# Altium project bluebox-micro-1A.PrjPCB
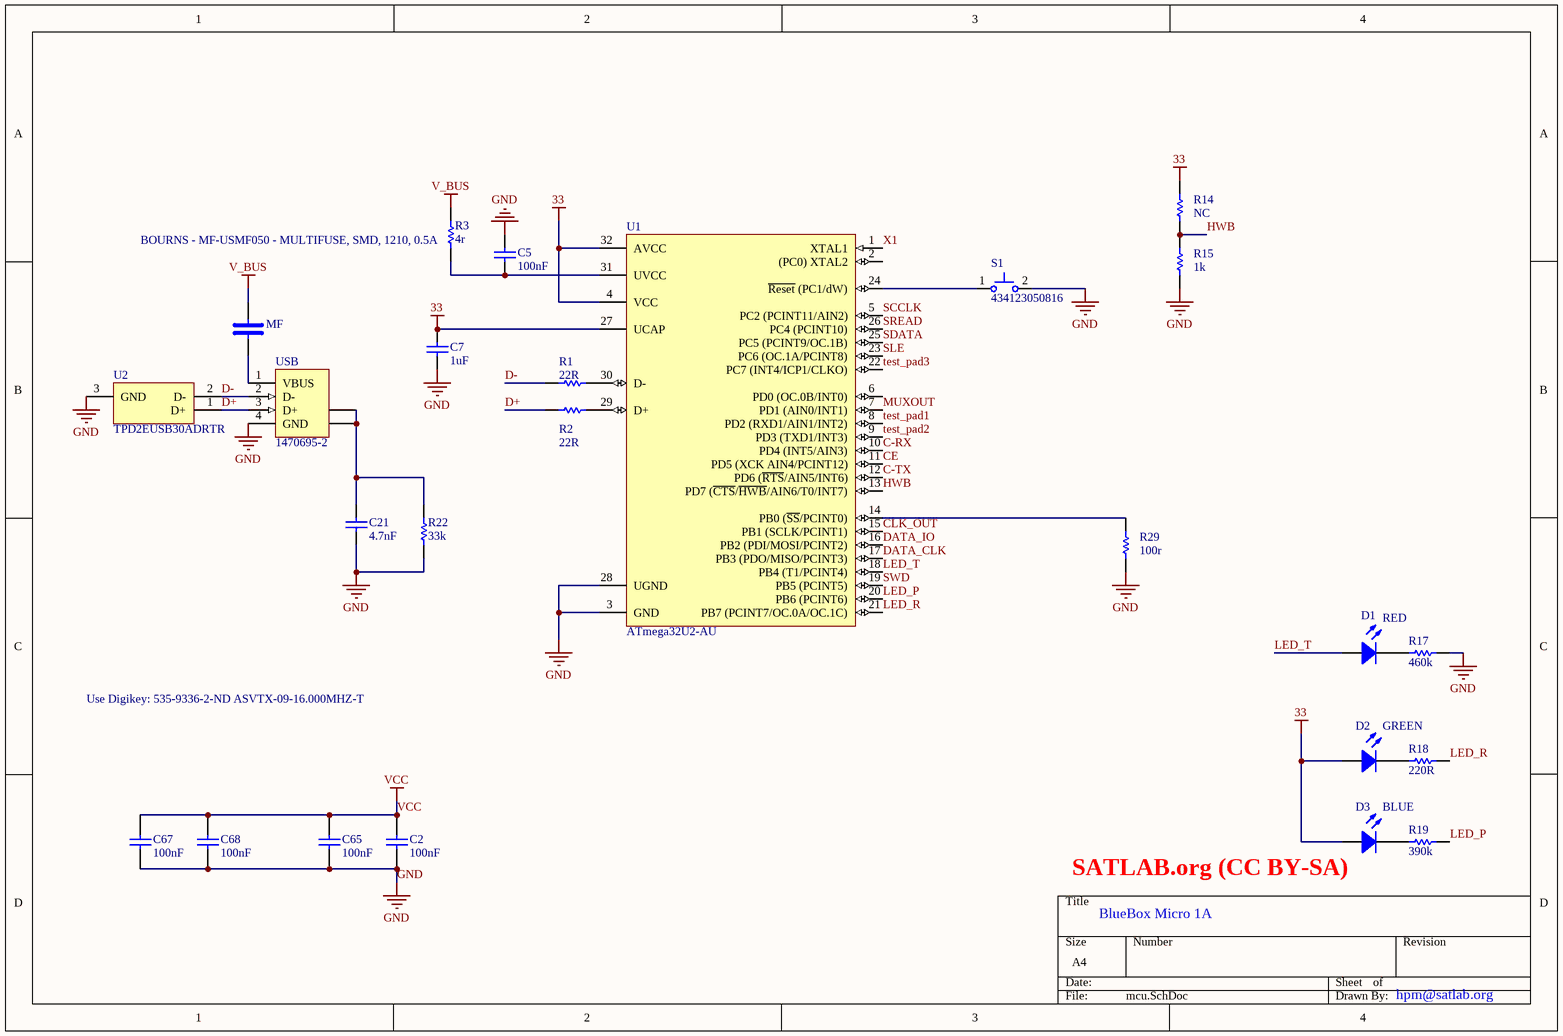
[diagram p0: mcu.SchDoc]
3 sheets, 97 parts. Net scope: global (net labels, ports and power ports of the same name join across sheets).
Board file: bluebox-micro-1A.PcbDoc
Sheets:
  mcu.SchDoc
  transceiver.SchDoc
  misc_rf.SchDoc

## Sheet mcu.SchDoc
size A4

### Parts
C2  value 100nF  [C06]  (hidden comment: Capacitor)
C5  value 100nF  [C06]  (hidden comment: Cap Semi)
C7  value 1uF  [C06]  (hidden comment: Cap Semi)
C21  value 4.7nF  [C06]  (hidden comment: Cap Semi)
C65  value 100nF  [C06]  (hidden comment: Capacitor)
C67  value 100nF  [C06]  (hidden comment: Capacitor)
C68  value 100nF  [C06]  (hidden comment: Capacitor)
D1  RED  [L06]
D2  GREEN  [L06]
D3  BLUE  [L06]
MF  CapacitorBig  [C1210]  (value not drawn)
R1  value 22R  [R06]  (hidden comment: Resistor)
R2  value 22R  [R06]  (hidden comment: Resistor)
R3  value 4r  [R06]  (hidden comment: Resistor)
R14  value NC  [R06]  (hidden comment: Resistor)
R15  value 1k  [R06]  (hidden comment: Resistor)
R17  value 460k  [R06]  (hidden comment: Resistor)
R18  value 220R  [R06]  (hidden comment: Resistor)
R19  value 390k  [R06]  (hidden comment: Resistor)
R22  value 33k  [R06]  (hidden comment: Resistor)
R29  value 100r  [R06]  (hidden comment: Resistor)
S1  434123050816  [spsd-raised]
U1  ATmega32U2-AU  [32A_L]
U2  TPD2EUSB30ADRTR  [DRT3]
USB  1470695-2  [1470695A]

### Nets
GND: C2.1 C5.1 C7.2 C21.2 C65.1 C67.1 C68.1 R15.1 R17.1 R22.2 R29.1 S1.2 U1.3(GND) U1.28(UGND) U2.3(GND) USB.4(GND)
V_BUS: MF.1 R3.1
VCC: C2.2 C7.1 C65.2 C67.2 C68.2 D2.1(A) D3.1(A) R14.2 U1.4(VCC) U1.27(UCAP) U1.32(AVCC)  [also labelled 33]
C-RX: U1.10(PD4_(INT5/AIN3))
C-TX: U1.12(PD6_(~{RTS}/AIN5/INT6))
CE: U1.11(PD5_(XCK_AIN4/PCINT12))
CLK_OUT: U1.15(PB1_(SCLK/PCINT1))
D+: R2.1 U2.1(D+) USB.3(D+)
D-: R1.2 U2.2(D-) USB.2(D-)
DATA_CLK: U1.17(PB3_(PDO/MISO/PCINT3))
DATA_IO: U1.16(PB2_(PDI/MOSI/PCINT2))
HWB: R14.1 R15.2 U1.13(PD7_(~{CTS}/~{HWB}/AIN6/T0/INT7))
LED_P: R19.1 U1.20(PB6_(PCINT6))
LED_R: R18.1 U1.21(PB7_(PCINT7/OC.0A/OC.1C))
LED_T: D1.1(A) U1.18(PB4_(T1/PCINT4))
MUXOUT: U1.7(PD1_(AIN0/INT1))
SCCLK: U1.5(PC2_(PCINT11/AIN2))
SDATA: U1.25(PC5_(PCINT9/OC.1B))
SLE: U1.23(PC6_(OC.1A/PCINT8))
SREAD: U1.26(PC4_(PCINT10))
SWD: U1.19(PB5_(PCINT5))
test_pad1: U1.8(PD2_(RXD1/AIN1/INT2))
test_pad2: U1.9(PD3_(TXD1/INT3))
test_pad3: U1.22(PC7_(INT4/ICP1/CLKO))
X1: U1.1(XTAL1)
NetC5_2: C5.2 R3.2 U1.31(UVCC)
NetC21_1: C21.1 R22.1 USB.5(SHLD) USB.6(SHLD)
NetD1_2: D1.2(K) R17.2
NetD2_2: D2.2(K) R18.2
NetD3_2: D3.2(K) R19.2
NetMF_2: MF.2 USB.1(VBUS)
NetR1_1: R1.1 U1.30(D-)
NetR2_2: R2.2 U1.29(D+)
NetR29_2: R29.2 U1.14(PB0_(~{SS}/PCINT0))
NetS1_1: S1.1 U1.24(~{Reset}_(PC1/dW))

Not connected (* = marked no-connect by the designer): U1 2((PC0)_XTAL2) 6(PD0_(OC.0B/INT0))

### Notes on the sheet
- (near R3) BOURNS - MF-USMF050 - MULTIFUSE, SMD, 1210, 0.5A
- Use Digikey: 535-9336-2-ND ASVTX-09-16.000MHZ-T
- (near D3) SATLAB.org (CC BY-SA)
- BlueBox Micro 1A
- hpm@satlab.org

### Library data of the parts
C2 C65 C67 C68 = Capacitor: Capacitor, standard
C5 C7 C21 = Cap Semi: Capacitor (Semiconductor SIM Model)
D1-D3 = LED: Typical RED GaAs LED
MF = CapacitorBig: Capacitor for PRU etc.; By: Troels Jessen; Username: tjessen
R1-R3 R14 R15 R17-R19 R22 R29 = Resistor: By: Troels Jessen; Username: tjessen
S1 = spsd-raised: Switch, Subminiature SMT, WURTH ELEKTRONIK - 434123050816 - SWITCH, 160GF, 6X3.5X5MM, BLK, J-BEND
U1 = ATmega32U2-AU: 8-bit AVR Microcontroller, 2.7-5.5V, 32KB Flash, 1KB EEPROM, 1KB SRAM, 32-pin TQFP, Industrial Grade (-40°C to 85°C)
U2 = TPD2EUSB30ADRTR: ESD / Surge Solution for High Speed, Low Voltage Interface, 2 Channels, -40 to +85 degC, 3-pin SOT (DRT), Green (RoHS & no Sb/Br); Manufacturer: Texas Instruments; 1394 / Firewire: TRUE; Breakdown Voltage(Min)(V): 4.5; Differential Capacitance(pF): 0.05; IEC 61000-4-2 Air-Gap(+/- kV): 8; IO Capacitance(Typ)(pF): 0.7; IO Leakage Current(nA): 10; SubFamily: ESD Solution
USB = 1470695-2: USB 1.1, Right Angle, SMT, A Type, Plug, 4 Position, Natural; ContactMaterial: Brass; ContactPlating: Gold (30) over Nickel (50); PCB_Layout: Complies with manufacturer's recommendation.; DrillSize: Corresponds to nominal value.; PanelGround: Without

## Sheet transceiver.SchDoc
size A3
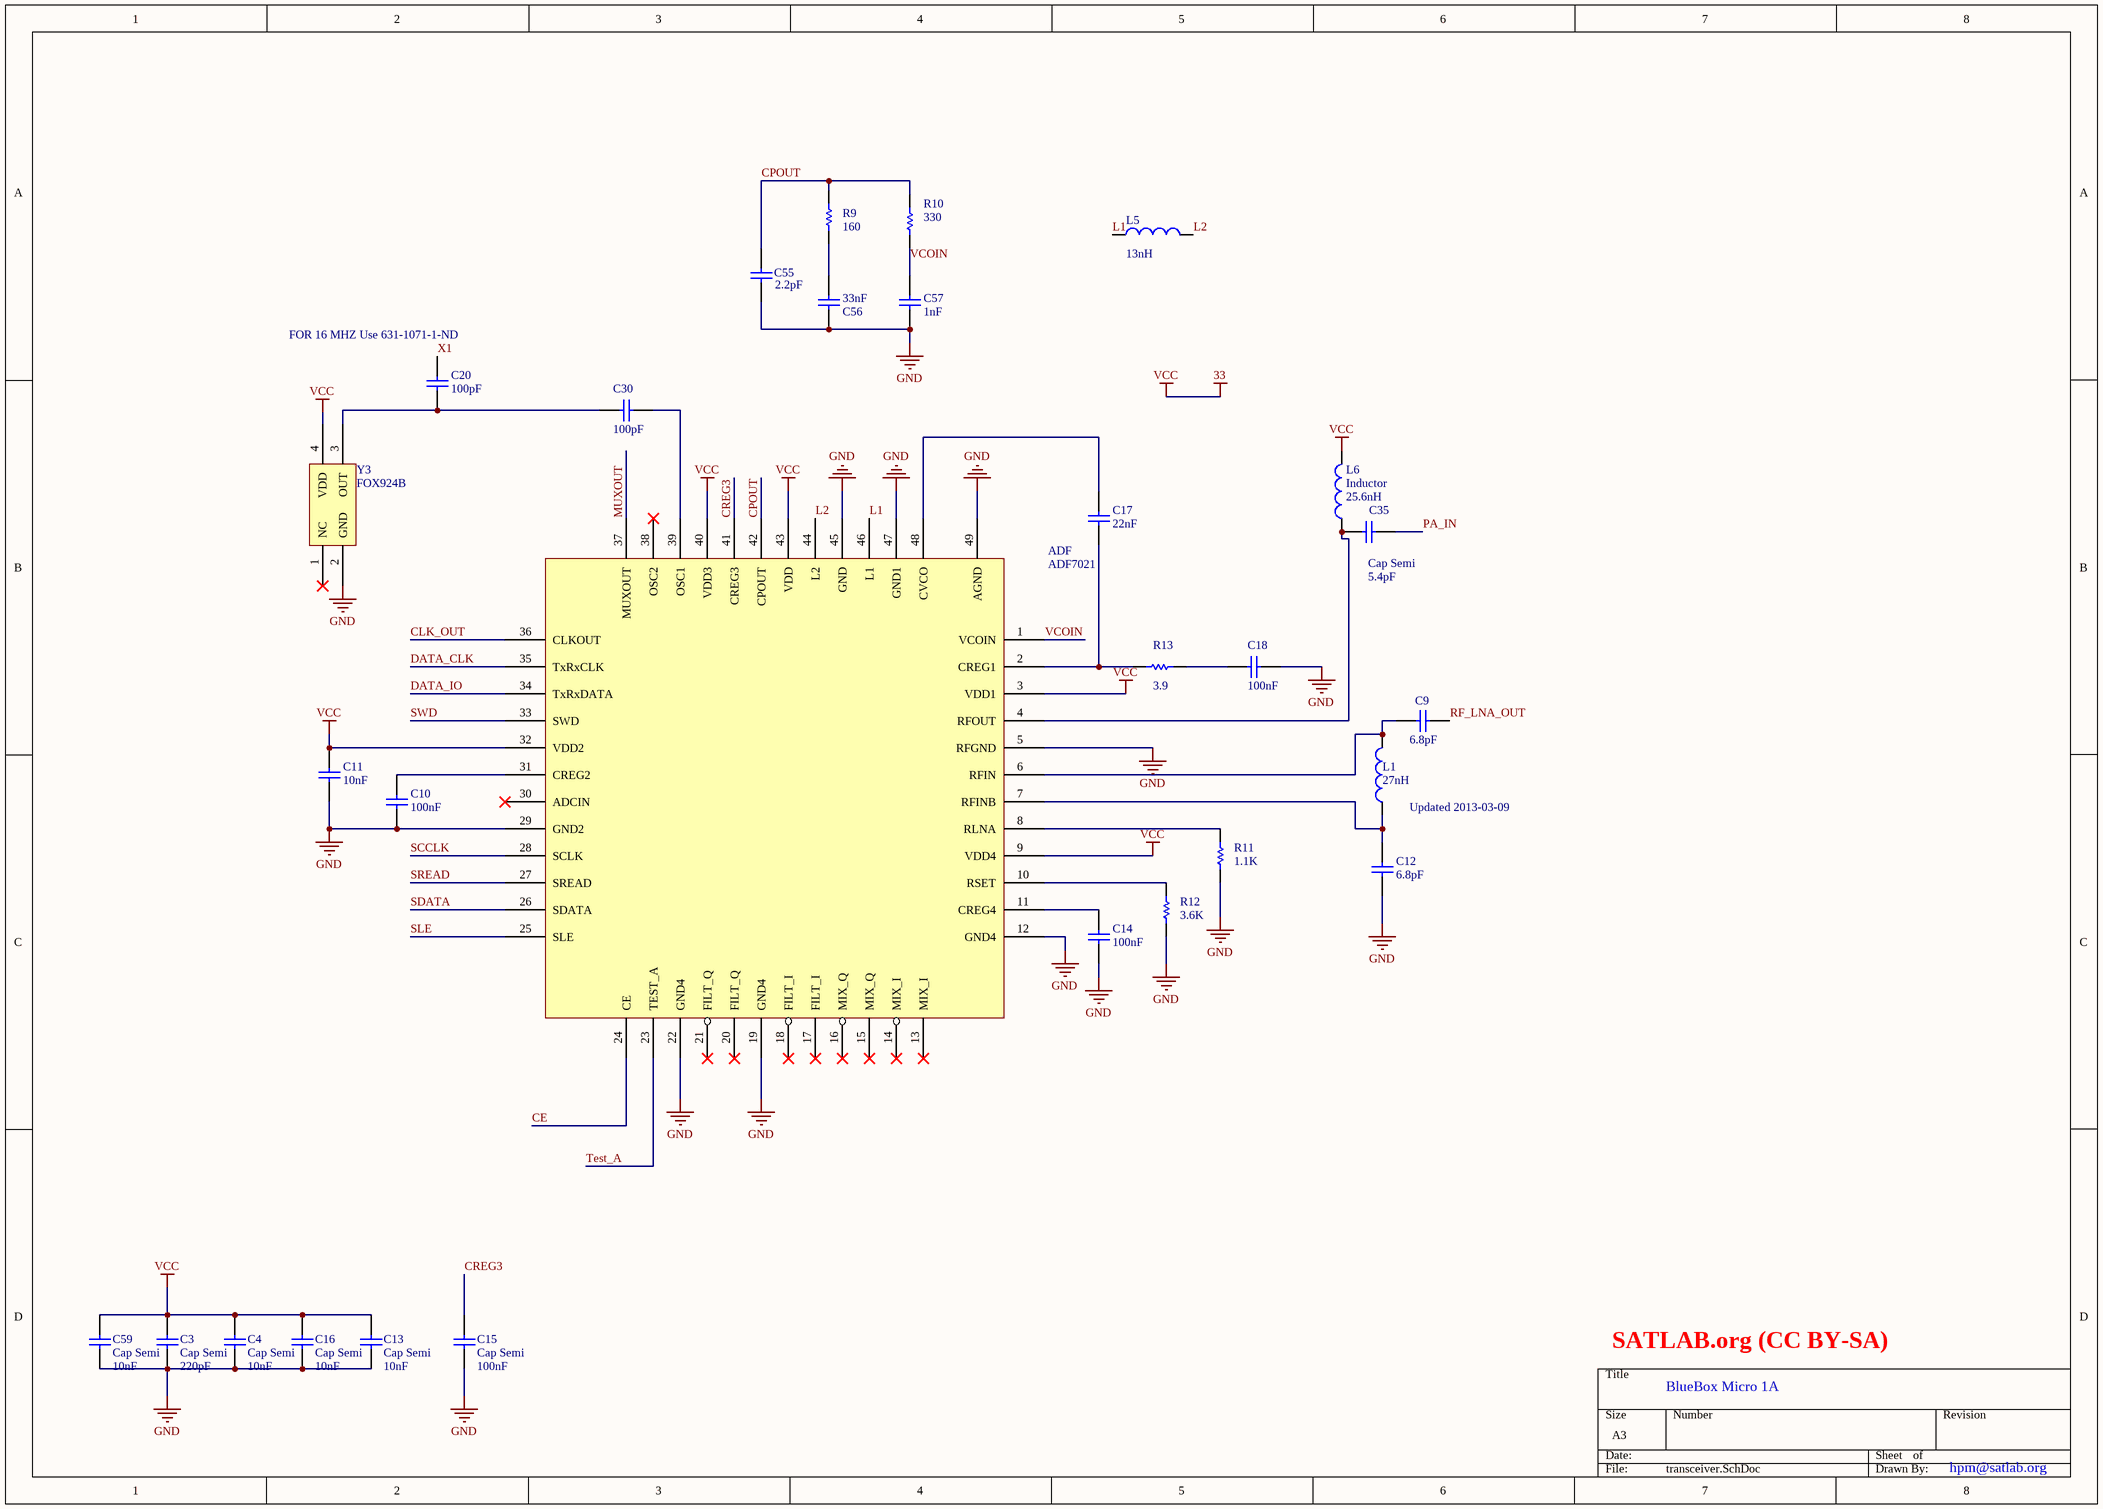
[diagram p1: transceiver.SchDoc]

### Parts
ADF  ADF7021  [QFN50P700X700X100-48M]
C3  Cap Semi  value 220pF  [C06]
C4  Cap Semi  value 10nF  [C06]
C9  value 6.8pF  [C06]  (hidden comment: Cap Semi)
C10  value 100nF  [C06]  (hidden comment: Cap Semi)
C11  value 10nF  [C06]  (hidden comment: Cap Semi)
C12  value 6.8pF  [C06]  (hidden comment: Cap Semi)
C13  Cap Semi  value 10nF  [C06]
C14  value 100nF  [C06]  (hidden comment: Cap Semi)
C15  Cap Semi  value 100nF  [C06]
C16  Cap Semi  value 10nF  [C06]
C17  value 22nF  [C06]  (hidden comment: Cap Semi)
C18  value 100nF  [C06]  (hidden comment: Cap Semi)
C20  value 100pF  [C06]  (hidden comment: Cap Semi)
C30  value 100pF  [C06]  (hidden comment: Cap Semi)
C35  Cap Semi  value 5.4pF  [C06]
C55  value 2.2pF  [C06]  (hidden comment: Cap Semi)
C56  value 33nF  [C06]  (hidden comment: Cap Semi)
C57  value 1nF  [C06]  (hidden comment: Cap Semi)
C59  Cap Semi  value 10nF  [C06]
L1  value 27nH  [C06]  (hidden comment: Inductor)
L5  value 13nH  [L06]  (hidden comment: Inductor)
L6  Inductor  value 25.6nH  [C06]
R9  value 160  [R06]  (hidden comment: Res Semi)
R10  value 330  [R06]  (hidden comment: Res Semi)
R11  value 1.1K  [R06]  (hidden comment: Res Semi)
R12  value 3.6K  [R06]  (hidden comment: Res Semi)
R13  value 3.9  [R06]  (hidden comment: Res Semi)
Y3  FOX924B  [Fox924]

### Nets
GND: ADF.5(RFGND) ADF.12(GND4) ADF.19(GND4) ADF.22(GND4) ADF.29(GND2) ADF.45(GND) ADF.47(GND1) ADF.49(AGND) C3.1 C4.1 C10.1 C11.1 C12.1 C13.1 C14.1 C15.1 C16.1 C18.2 C55.1 C56.1 C57.1 C59.1 R11.2 R12.1 Y3.2(GND)
VCC: ADF.3(VDD1) ADF.9(VDD4) ADF.32(VDD2) ADF.40(VDD3) ADF.43(VDD) C3.2 C4.2 C11.2 C13.2 C16.2 C59.2 L6.2 Y3.4(VDD)  [also labelled 33]
CE: ADF.24(CE)
CLK_OUT: ADF.36(CLKOUT)
CPOUT: ADF.42(CPOUT) C55.2 R9.2 R10.2
CREG3: ADF.41(CREG3) C15.2
DATA_CLK: ADF.35(TxRxCLK)
DATA_IO: ADF.34(TxRxDATA)
L1: ADF.46(L1) L5.1
L2: ADF.44(L2) L5.2
MUXOUT: ADF.37(MUXOUT)
PA_IN: C35.2
RF_LNA_OUT: C9.1
SCCLK: ADF.28(SCLK)
SDATA: ADF.26(SDATA)
SLE: ADF.25(SLE)
SREAD: ADF.27(SREAD)
SWD: ADF.33(SWD)
Test_A: ADF.23(TEST_A)
VCOIN: ADF.1(VCOIN) C57.2 R10.1
X1: C20.2
NetADF_2: ADF.2(CREG1) C17.1 R13.1
NetADF_4: ADF.4(RFOUT) C35.1 L6.1
NetADF_6: ADF.6(RFIN) C9.2 L1.2
NetADF_7: ADF.7(RFINB) C12.2 L1.1
NetADF_8: ADF.8(RLNA) R11.1
NetADF_10: ADF.10(RSET) R12.2
NetADF_11: ADF.11(CREG4) C14.2
NetADF_31: ADF.31(CREG2) C10.2
NetADF_39: ADF.39(OSC1) C30.2
NetADF_48: ADF.48(CVCO) C17.2
NetC18_1: C18.1 R13.2
NetC20_1: C20.1 C30.1 Y3.3(OUT)
NetC56_2: C56.2 R9.1

Not connected (* = marked no-connect by the designer): ADF 13(MIX_I)* 14(MIX_I)* 15(MIX_Q)* 16(MIX_Q)* 17(FILT_I)* 18(FILT_I)* 20(FILT_Q)* 21(FILT_Q)* 30(ADCIN)* 38(OSC2)*; Y3 1(NC)*

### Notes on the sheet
- Using http://www.calculatoredge.com/electronics/ch%20pi%20low%20pass.htm
- (near C20) FOR 16 MHZ Use 631-1071-1-ND
- Using http://bwrc.eecs.berkeley.edu/research/rf/projects/60ghz/matching/impmatch.html
- (near L1) Updated 2013-03-09
- SATLAB.org (CC BY-SA)
- BlueBox Micro 1A
- hpm@satlab.org

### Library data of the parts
ADF = ADF7021: ADF7021 transceiver; By: Nikolaj Bisgaard Pedersen
C3 C4 C9-C18 C20 C30 C35 C55-C57 C59 = Cap Semi: Capacitor (Semiconductor SIM Model)
L5 = Inductor: Code_IEC: 1005
R9-R13 = Res Semi: Semiconductor Resistor
Y3 = FOX924B: FOX924B TCXO 19.44 MHz; By: Nikolaj B. Pedersen; Username: Markem

## Sheet misc_rf.SchDoc
size A4
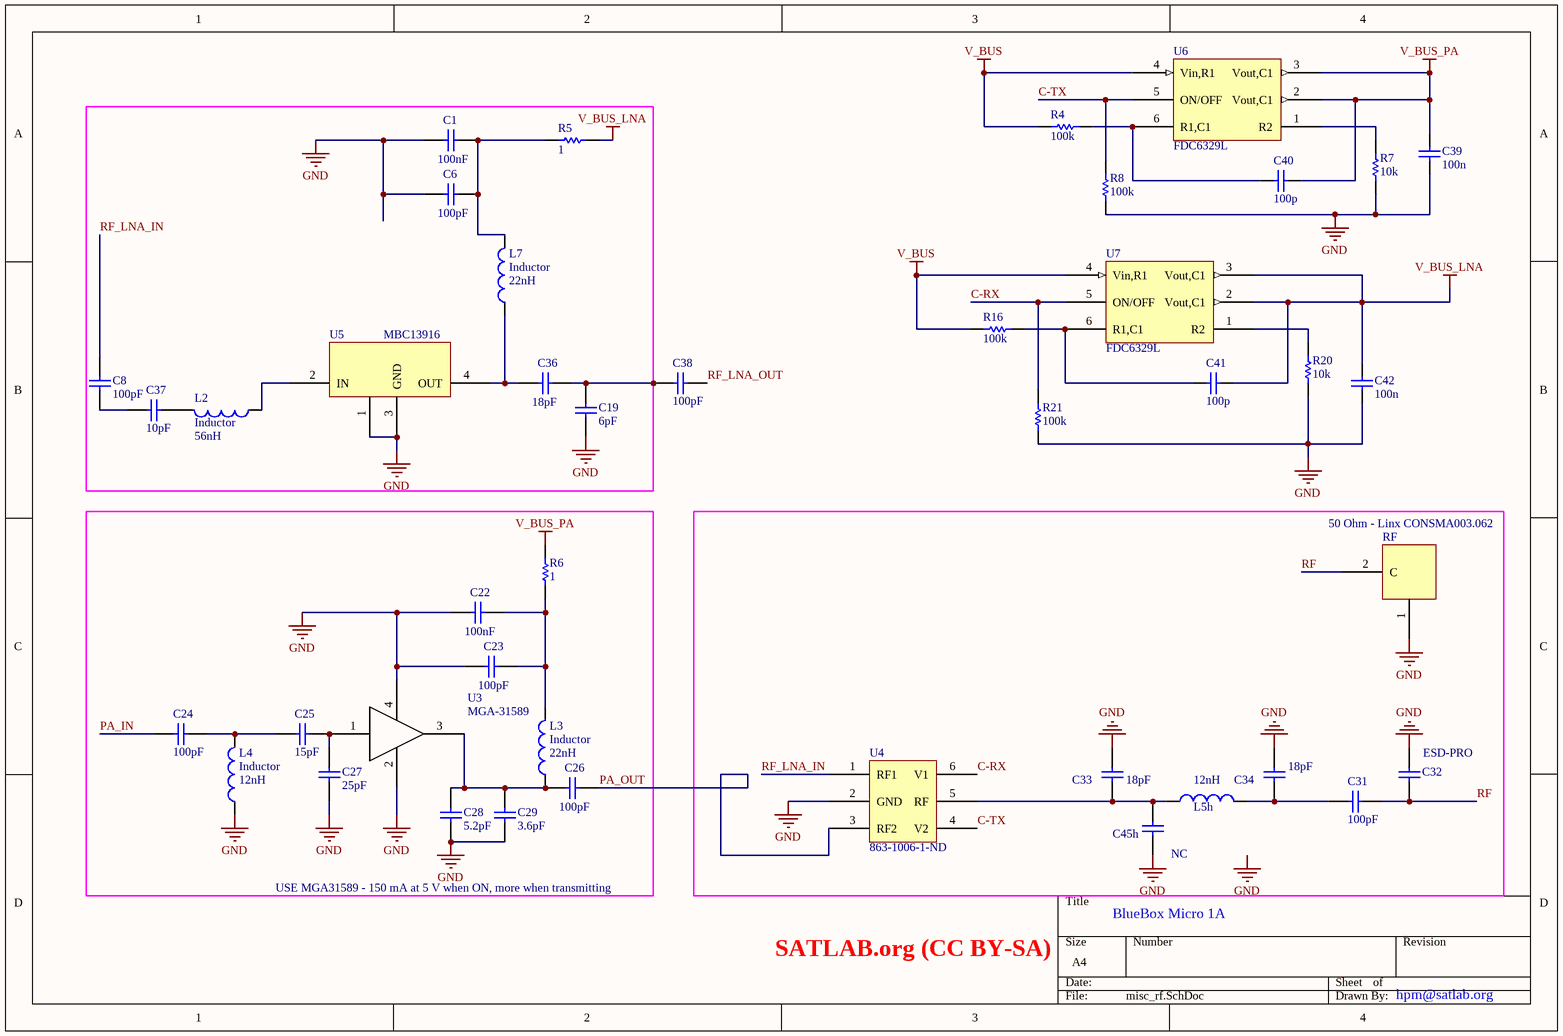
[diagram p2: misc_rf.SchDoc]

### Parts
C1  value 100nF  [C06]  (hidden comment: Cap Semi)
C6  value 100pF  [C06]  (hidden comment: Cap Semi)
C8  value 100pF  [C06]  (hidden comment: Cap Semi)
C19  value 6pF  [C06]  (hidden comment: Cap Semi)
C22  value 100nF  [C06]  (hidden comment: Cap Semi)
C23  value 100pF  [C06]  (hidden comment: Cap Semi)
C24  value 100pF  [C06]  (hidden comment: Cap Semi)
C25  value 15pF  [C06]  (hidden comment: Cap Semi)
C26  value 100pF  [C06]  (hidden comment: Cap Semi)
C27  value 25pF  [C06]  (hidden comment: Cap Semi)
C28  value 5.2pF  [C06]  (hidden comment: Cap Semi)
C29  value 3.6pF  [C06]  (hidden comment: Cap Semi)
C31  value 100pF  [C06]  (hidden comment: Capacitor)
C32  value ESD-PRO  [C06]  (hidden comment: Capacitor)
C33  value 18pF  [C06]  (hidden comment: Cap Semi)
C34  value 18pF  [C06]  (hidden comment: Cap Semi)
C36  value 18pF  [C06]  (hidden comment: Cap Semi)
C37  value 10pF  [C06]  (hidden comment: Cap Semi)
C38  value 100pF  [C06]  (hidden comment: Cap Semi)
C39  value 100n  [C06]  (hidden comment: Capacitor)
C40  value 100p  [C06]  (hidden comment: Capacitor)
C41  value 100p  [C06]  (hidden comment: Capacitor)
C42  value 100n  [C06]  (hidden comment: Capacitor)
C45h  value NC  [C06]  (hidden comment: Cap Semi)
L2  Inductor  value 56nH  [C06]
L3  Inductor  value 22nH  [C06]
L4  Inductor  value 12nH  [C06]
L5h  value 12nH  [C06]  (hidden comment: Inductor)
L7  Inductor  value 22nH  [C06]
R4  value 100k  [R06]  (hidden comment: Resistor)
R5  value 1  [R06]  (hidden comment: Resistor)
R6  value 1  [R06]  (hidden comment: Resistor)
R7  value 10k  [R06]  (hidden comment: Resistor)
R8  value 100k  [R06]  (hidden comment: Resistor)
R16  value 100k  [R06]  (hidden comment: Resistor)
R20  value 10k  [R06]  (hidden comment: Resistor)
R21  value 100k  [R06]  (hidden comment: Resistor)
RF  50 Ohm - Linx CONSMA003.062  [sma-egde]
U3  MGA-31589  [SOT-223B-small]
U4  Supplier Part Number 1: 863-1006-1-ND  [SOT95P280X145-6N]  (hidden comment: AS193-73)
U5  MBC13916  [MBC13916]
U6  FDC6329L  [SSOT-6]
U7  FDC6329L  [SSOT-6]

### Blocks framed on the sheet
USE MGA31589 - 150 mA at 5 V when ON, more when transmitting: C22-C29 L3 L4 R6 U3

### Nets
GND: C1.2 C6.2 C19.2 C22.2 C23.2 C27.1 C28.2 C29.2 C32.1 C33.2 C34.2 C39.1 C42.1 C45h.1 L4.1 R7.1 R8.1 R20.1 R21.1 RF.1(GND) U3.2(GND) U3.4(GND) U4.2(GND) U5.1(GND) U5.3(GND)
V_BUS: R4.2 R16.2 U6.4(Vin,R1) U7.4(Vin,R1)
V_BUS_LNA: C41.1 C42.2 R5.2 U7.2(Vout,C1) U7.3(Vout,C1)
V_BUS_PA: C39.2 C40.1 R6.2 U6.2(Vout,C1) U6.3(Vout,C1)
C-RX: R21.2 U4.6(V1) U7.5(ON/OFF)
C-TX: R8.2 U4.4(V2) U6.5(ON/OFF)
PA_IN: C24.1
PA_OUT: C26.1 U4.3(RF2)
RF: C31.1 C32.2 RF.2(C)
RF_LNA_IN: C8.1 U4.1(RF1)
RF_LNA_OUT: C38.2
NetC1_1: C1.1 C6.1 L7.2 R5.1
NetC8_2: C8.2 C37.1
NetC19_1: C19.1 C36.1 C38.1
NetC22_1: C22.1 C23.1 L3.2 R6.1
NetC24_2: C24.2 C25.1 L4.2
NetC25_2: C25.2 C27.2 U3.1(RF_IN)
NetC26_2: C26.2 C28.1 C29.1 L3.1 U3.3(RF_OUT)
NetC31_2: C31.2 C34.1 L5h.2
NetC33_1: C33.1 C45h.2 L5h.1 U4.5(RF)
NetC36_2: C36.2 L7.1 U5.4(OUT)
NetC37_2: C37.2 L2.2
NetC40_2: C40.2 R4.1 U6.6(R1,C1)
NetC41_2: C41.2 R16.1 U7.6(R1,C1)
NetL2_1: L2.1 U5.2(IN)
NetR7_2: R7.2 U6.1(R2)
NetR20_2: R20.2 U7.1(R2)

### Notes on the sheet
- BlueBox Micro 1A
- SATLAB.org (CC BY-SA)
- hpm@satlab.org
- Labels drawn without touching a wire or pin: GND

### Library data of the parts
C1 C6 C8 C19 C22-C29 C33 C34 C36-C38 C45h = Cap Semi: Capacitor (Semiconductor SIM Model)
C31 C32 C39-C42 = Capacitor: Capacitor, standard
R4-R8 R16 R20 R21 = Resistor: By: Troels Jessen; Username: tjessen
RF = SMA_BOARD_EGDE: Linx CONSMA003.062  -  SMA Female Edge Mount for 1.6 mm PCB
U3 = MGA-31589: 0.5 W High Gain Driver Amplifier
U4 = AS193-73: PHEMT GaAs IC High-Linearity 3 V  Control SPDT Switch 0.1–2.5 GHz; By: HP
U6 U7 = FDC6329L: Integrated Load Switch

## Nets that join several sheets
GND: mcu (16 pins), transceiver (25 pins), misc_rf (25 pins)
V_BUS: mcu (MF.1 R3.1), misc_rf (R4.2 R16.2 U6.4 U7.4)
VCC: mcu (11 pins), transceiver (13 pins)
C-RX: mcu (U1.10), misc_rf (R21.2 U4.6 U7.5)
C-TX: mcu (U1.12), misc_rf (R8.2 U4.4 U6.5)
CE: mcu (U1.11), transceiver (ADF.24)
CLK_OUT: mcu (U1.15), transceiver (ADF.36)
DATA_CLK: mcu (U1.17), transceiver (ADF.35)
DATA_IO: mcu (U1.16), transceiver (ADF.34)
MUXOUT: mcu (U1.7), transceiver (ADF.37)
PA_IN: transceiver (C35.2), misc_rf (C24.1)
RF_LNA_OUT: transceiver (C9.1), misc_rf (C38.2)
SCCLK: mcu (U1.5), transceiver (ADF.28)
SDATA: mcu (U1.25), transceiver (ADF.26)
SLE: mcu (U1.23), transceiver (ADF.25)
SREAD: mcu (U1.26), transceiver (ADF.27)
SWD: mcu (U1.19), transceiver (ADF.33)
X1: mcu (U1.1), transceiver (C20.2)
